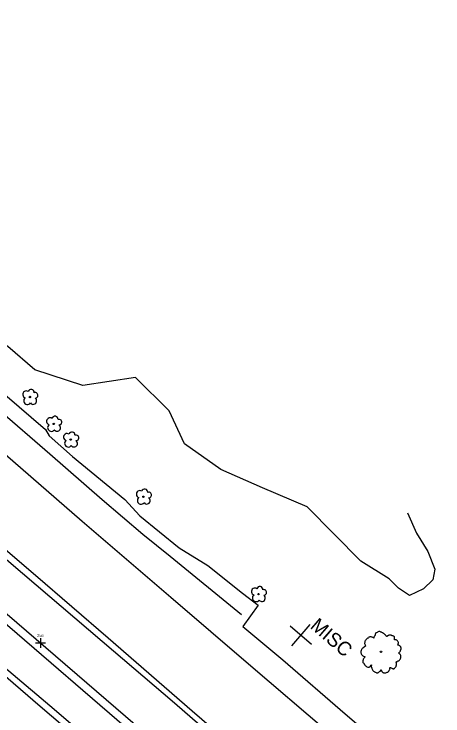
# Model space of a CAD drawing. Extents: x 2076109 to 2080761, y 592812 to 596750.
# Drawn here: x 2079834.4 to 2079987.8, y 593575.6 to 593826.9 of the extents above; entities that cross this region are included whole.
import ezdxf

# ---------------------------------------------------------------- set-up
doc = ezdxf.new("R2010")
doc.units = 0
for name, color, linetype in [('Default', 7, 'Continuous'), ('RD_EX_GuardRail', 7, 'Continuous'), ('RD_EX_Misc', 7, 'Continuous'), ('RD_EX_Misc_txCode', 7, 'Continuous'), ('RD_EX_Road', 7, 'Continuous'), ('RD_EX_VEG', 7, 'Continuous'), ('RD_HC_Cl', 7, 'Continuous')]:
    doc.layers.add(name, color=color, linetype=linetype)

msp = doc.modelspace()

# ---------------------------------------------------------------- linework, layer by layer
at = {"layer": 'Default'}
for p, q in [((2079843.82, 593603.43), (2079843.82, 593599.93)), ((2079843.82, 593603.43), (2079843.82, 593599.93)), ((2079845.57, 593601.68), (2079842.07, 593601.68)), ((2079845.57, 593601.68), (2079842.07, 593601.68))]:
    msp.add_line(p, q, dxfattribs=at)
at = {"layer": 'RD_EX_GuardRail'}
for points in [[(2080184.35, 593305.04), (2080148.2, 593335.86), (2080111.67, 593367.26), (2080075.44, 593398.3), (2080039.84, 593429.28), (2080003.46, 593460.74), (2079967.36, 593491.67), (2079919.17, 593532.83), (2079871.19, 593574.23), (2079835.53, 593605.02), (2079799.41, 593635.93), (2079763.16, 593666.95), (2079727.5, 593697.27), (2079690.37, 593729.2), (2079655.55, 593758.99), (2079608.01, 593799.67)], [(2079915.69, 593611.77), (2079890.2, 593632.66), (2079880.48, 593640.55), (2079865.92, 593652.95), (2079847.21, 593669.28), (2079828.34, 593685.59), (2079804.41, 593705.91), (2079785.94, 593721.98), (2079757.68, 593746.46), (2079723.46, 593776.29)], [(2079915.69, 593611.77), (2079890.2, 593632.66), (2079880.48, 593640.55), (2079865.92, 593652.95), (2079847.21, 593669.28), (2079828.34, 593685.59), (2079804.41, 593705.91), (2079785.94, 593721.98), (2079757.68, 593746.46), (2079723.46, 593776.29)]]:
    msp.add_lwpolyline(points, dxfattribs=at)
at = {"layer": 'RD_EX_Misc'}
for p, q in [((2079933.2, 593607.81), (2079940.76, 593601.27)), ((2079933.2, 593607.81), (2079940.76, 593601.27)), ((2079933.71, 593600.76), (2079940.25, 593608.33)), ((2079933.71, 593600.76), (2079940.25, 593608.33))]:
    msp.add_line(p, q, dxfattribs=at)
for points in [[(2080217.04, 593337.18), (2080172.52, 593375.33), (2080138.87, 593404.33), (2080108.48, 593430.29), (2080078.14, 593456.52), (2080038.92, 593490.11), (2080009.05, 593515.98), (2079977.29, 593543.26), (2079946.15, 593570.28), (2079919.11, 593593.43), (2079890.41, 593617.97), (2079858.75, 593645.26), (2079821.86, 593677.15), (2079782.12, 593711.42), (2079735.64, 593751.71), (2079701.45, 593781.37), (2079664.35, 593813.72), (2079643.76, 593831.64)], [(2079627.11, 593812.28), (2079655.96, 593786.97), (2079692.98, 593754.86), (2079726.56, 593725.77), (2079758.83, 593697.63), (2079788.04, 593672.28), (2079811.24, 593652.3), (2079842, 593625.98), (2079868.07, 593603.53), (2079898.03, 593577.49), (2079923.97, 593555.11), (2079945.84, 593536.38), (2079972.92, 593513.01), (2079994.98, 593494.07), (2080016.85, 593475.02), (2080049.11, 593447.31), (2080079.81, 593420.95), (2080112.25, 593393.22), (2080144.25, 593365.64), (2080177.02, 593337.45), (2080203.16, 593314.91)], [(2080178.72, 593290.98), (2080145.52, 593319.67), (2080116.25, 593344.84), (2080082.12, 593374.03), (2080051.53, 593400.34), (2080021.2, 593426.66), (2079989.82, 593453.61), (2079954.27, 593484.21), (2079917.77, 593515.59), (2079872.88, 593554.03), (2079843.75, 593579.04), (2079811.01, 593607.11), (2079771.89, 593640.76), (2079736.28, 593671.46), (2079708.41, 593695.19), (2079678.65, 593720.6), (2079637.6, 593755.82), (2079606.82, 593782.2)]]:
    msp.add_lwpolyline(points, dxfattribs=at)
at = {"layer": 'RD_EX_Road'}
for points in [[(2079915.58, 593559.4), (2079891.77, 593580.17), (2079865.9, 593602.21), (2079832.47, 593630.76), (2079804.37, 593655.14), (2079781.34, 593675), (2079764.28, 593689.81), (2079743.82, 593707.18), (2079725.61, 593722.92), (2079710.62, 593736.11), (2079695.41, 593749.27), (2079683.78, 593759.65), (2079664.93, 593775.72), (2079643.32, 593794.49), (2079625.35, 593810.82)], [(2079603.88, 593788.4), (2079630.41, 593765.74), (2079649.64, 593748.83), (2079670, 593731.78), (2079695.31, 593710.54), (2079705.57, 593701.2), (2079723.39, 593685.71), (2079744.81, 593667.42), (2079757.22, 593656.6), (2079776.93, 593639.55), (2079797.54, 593621.87), (2079819.28, 593602.83), (2079847.19, 593579.3), (2079876.99, 593553.77)], [(2079831.04, 593690.71), (2079845.61, 593678.16), (2079846.92, 593675.92), (2079855.23, 593668.45), (2079873.95, 593653.14), (2079879.4, 593647.23), (2079893.41, 593635.8), (2079903.73, 593629.47), (2079916.08, 593619.54), (2079921.67, 593615.3), (2079916.27, 593607.61), (2079930.48, 593595.65), (2079952.79, 593576.41), (2079973.53, 593558.52)]]:
    msp.add_lwpolyline(points, dxfattribs=at)
at = {"layer": 'RD_EX_VEG'}
for points in [[(2079968.58, 593624.66), (2079958.38, 593631.05), (2079939.2, 593650.42), (2079923.3, 593657.31), (2079908.32, 593663.78), (2079895.34, 593672.97), (2079889.9, 593684.89), (2079877.81, 593696.83), (2079858.95, 593693.87), (2079841.76, 593699.48), (2079832.11, 593707.82), (2079816.9, 593723.01), (2079799.06, 593733.44), (2079782.58, 593737.31), (2079774.16, 593743.85), (2079774.4, 593750.13), (2079779.63, 593760.24), (2079784.95, 593777.32), (2079790.58, 593800.97), (2079790.86, 593805.75)], [(2079968.58, 593624.66), (2079958.38, 593631.05), (2079939.2, 593650.42), (2079923.3, 593657.31), (2079908.32, 593663.78), (2079895.34, 593672.97), (2079889.9, 593684.89), (2079877.81, 593696.83), (2079858.95, 593693.87), (2079841.76, 593699.48), (2079832.11, 593707.82), (2079816.9, 593723.01), (2079799.06, 593733.44), (2079782.58, 593737.31), (2079774.16, 593743.85), (2079774.4, 593750.13), (2079779.63, 593760.24), (2079784.95, 593777.32), (2079790.58, 593800.97), (2079790.86, 593805.75)], [(2079975.08, 593648.34), (2079978.3, 593640.99), (2079982.45, 593634.44), (2079984.88, 593628.11), (2079984.16, 593624.28), (2079980.91, 593621.16), (2079975.82, 593618.71), (2079971.96, 593621.31), (2079968.58, 593624.66)], [(2079975.08, 593648.34), (2079978.3, 593640.99), (2079982.45, 593634.44), (2079984.88, 593628.11), (2079984.16, 593624.28), (2079980.91, 593621.16), (2079975.82, 593618.71), (2079971.96, 593621.31), (2079968.58, 593624.66)]]:
    msp.add_lwpolyline(points, dxfattribs=at)
for centre, radius in [((2079840.01, 593689.79), 0.25), ((2079840.01, 593689.79), 0.25), ((2079848.55, 593680.18), 0.25), ((2079848.55, 593680.18), 0.25), ((2079854.62, 593674.56), 0.25), ((2079854.62, 593674.56), 0.25), ((2079880.65, 593654.09), 0.25), ((2079880.65, 593654.09), 0.25), ((2079921.82, 593619.23), 0.25), ((2079921.82, 593619.23), 0.25), ((2079965.64, 593598.57), 0.25), ((2079965.64, 593598.57), 0.25), ((2079965.62, 593598.56), 0.0001), ((2079965.62, 593598.56), 0.0001)]:
    msp.add_circle(centre, radius, dxfattribs=at)
for centre, radius, start, end in [((2079840.47, 593691.43), 1.08, 354.1438, 163.9235), ((2079840.47, 593691.43), 1.08, 354.1438, 163.9235), ((2079838.72, 593690.69), 1.26, 55.6193, 253.9015), ((2079838.72, 593690.69), 1.26, 55.6193, 253.9015), ((2079841.91, 593690.39), 0.995, 267.9301, 111.2143), ((2079841.91, 593690.39), 0.995, 267.9301, 111.2143), ((2079839.15, 593688.42), 1.32, 126.0502, 324.9265), ((2079839.15, 593688.42), 1.32, 126.0502, 324.9265), ((2079841.22, 593688.37), 1.22, 215.7342, 57.2722), ((2079841.22, 593688.37), 1.22, 215.7342, 57.2722), ((2079847.27, 593681.08), 1.26, 55.6193, 253.9015), ((2079847.27, 593681.08), 1.26, 55.6193, 253.9015), ((2079849.02, 593681.82), 1.08, 354.1438, 163.9235), ((2079849.02, 593681.82), 1.08, 354.1438, 163.9235), ((2079847.7, 593678.81), 1.32, 126.0502, 324.9265), ((2079847.7, 593678.81), 1.32, 126.0502, 324.9265), ((2079849.76, 593678.76), 1.22, 215.7342, 57.2722), ((2079849.76, 593678.76), 1.22, 215.7342, 57.2722), ((2079850.46, 593680.78), 0.995, 267.9301, 111.2143), ((2079850.46, 593680.78), 0.995, 267.9301, 111.2143), ((2079855.09, 593676.2), 1.08, 354.1438, 163.9235), ((2079855.09, 593676.2), 1.08, 354.1438, 163.9235), ((2079853.34, 593675.46), 1.26, 55.6193, 253.9015), ((2079853.34, 593675.46), 1.26, 55.6193, 253.9015), ((2079856.53, 593675.16), 0.995, 267.9301, 111.2143), ((2079856.53, 593675.16), 0.995, 267.9301, 111.2143), ((2079853.77, 593673.19), 1.32, 126.0502, 324.9265), ((2079853.77, 593673.19), 1.32, 126.0502, 324.9265), ((2079855.83, 593673.14), 1.22, 215.7342, 57.2722), ((2079855.83, 593673.14), 1.22, 215.7342, 57.2722), ((2079879.36, 593655), 1.26, 55.6193, 253.9015), ((2079879.36, 593655), 1.26, 55.6193, 253.9015), ((2079881.11, 593655.73), 1.08, 354.1438, 163.9235), ((2079881.11, 593655.73), 1.08, 354.1438, 163.9235), ((2079882.55, 593654.7), 0.995, 267.9301, 111.2143), ((2079882.55, 593654.7), 0.995, 267.9301, 111.2143), ((2079879.79, 593652.72), 1.32, 126.0502, 324.9265), ((2079879.79, 593652.72), 1.32, 126.0502, 324.9265), ((2079881.86, 593652.68), 1.22, 215.7342, 57.2722), ((2079881.86, 593652.68), 1.22, 215.7342, 57.2722), ((2079922.29, 593620.87), 1.08, 354.1438, 163.9235), ((2079922.29, 593620.87), 1.08, 354.1438, 163.9235), ((2079920.54, 593620.13), 1.26, 55.6193, 253.9015), ((2079920.54, 593620.13), 1.26, 55.6193, 253.9015), ((2079923.72, 593619.83), 0.995, 267.9301, 111.2143), ((2079923.72, 593619.83), 0.995, 267.9301, 111.2143), ((2079920.96, 593617.86), 1.32, 126.0502, 324.9265), ((2079920.96, 593617.86), 1.32, 126.0502, 324.9265), ((2079923.03, 593617.81), 1.22, 215.7342, 57.2722), ((2079923.03, 593617.81), 1.22, 215.7342, 57.2722)]:
    msp.add_arc(centre, radius, start, end, dxfattribs=at)
for points in [[(2079970.43, 593603.9), (2079970.22, 593604.12), (2079969.91, 593604.25), (2079969.65, 593604.34), (2079969.43, 593604.43), (2079969.2, 593604.5), (2079968.85, 593604.57), (2079968.55, 593604.56), (2079968.3, 593604.46), (2079968.11, 593604.32), (2079967.89, 593604.14), (2079967.78, 593604.01), (2079967.67, 593604.07), (2079967.57, 593604.19), (2079967.43, 593604.41), (2079967.24, 593604.57), (2079967.05, 593604.74), (2079966.77, 593604.95), (2079966.51, 593605.18), (2079966.27, 593605.32), (2079965.99, 593605.49), (2079965.62, 593605.64), (2079965.28, 593605.78), (2079964.89, 593605.78), (2079964.39, 593605.59), (2079964.06, 593605.4), (2079963.79, 593605.31), (2079963.61, 593604.88), (2079963.51, 593604.5), (2079963.4, 593604.33), (2079963.18, 593603.96), (2079963.11, 593603.72), (2079963.07, 593603.49), (2079963, 593603.52), (2079962.68, 593603.73), (2079962.39, 593603.85), (2079961.92, 593603.96), (2079961.6, 593603.93), (2079961.31, 593603.75), (2079961.07, 593603.5), (2079960.86, 593603.42), (2079960.62, 593603.26), (2079960.56, 593603.22), (2079960.31, 593603), (2079960.09, 593602.6), (2079959.88, 593602.32), (2079959.82, 593602.07), (2079959.82, 593601.84), (2079959.79, 593601.53), (2079959.95, 593601.1), (2079960.13, 593600.81), (2079960.26, 593600.66), (2079959.8, 593600.4), (2079959.54, 593600.17), (2079959.18, 593599.95), (2079959.13, 593599.89), (2079958.78, 593599.56), (2079958.69, 593599.22), (2079958.5, 593598.89), (2079958.48, 593598.6), (2079958.49, 593598.2), (2079958.59, 593597.81), (2079958.89, 593597.39), (2079959.21, 593597.15), (2079959.76, 593596.91), (2079960, 593596.8), (2079959.86, 593596.68), (2079959.64, 593596.38), (2079959.36, 593596.06), (2079959.26, 593595.72), (2079959.16, 593595.44), (2079959.11, 593595.16), (2079959.2, 593594.77), (2079959.46, 593594.46), (2079959.68, 593594.07), (2079959.97, 593593.71), (2079960.33, 593593.37), (2079960.89, 593593.09), (2079961.18, 593593.01), (2079961.37, 593593.07), (2079961.76, 593593.22), (2079961.87, 593593.43), (2079962.28, 593593.87), (2079962.24, 593593.67), (2079962.15, 593593.29), (2079962.33, 593592.73), (2079962.52, 593592.34), (2079962.78, 593591.92), (2079962.96, 593591.66), (2079963.36, 593591.41), (2079963.7, 593591.22), (2079964.06, 593591.07), (2079964.47, 593591.08), (2079964.78, 593591.18), (2079965, 593591.35), (2079965.3, 593591.59), (2079965.45, 593591.69)], [(2079970.43, 593603.9), (2079970.22, 593604.12), (2079969.91, 593604.25), (2079969.65, 593604.34), (2079969.43, 593604.43), (2079969.2, 593604.5), (2079968.85, 593604.57), (2079968.55, 593604.56), (2079968.3, 593604.46), (2079968.11, 593604.32), (2079967.89, 593604.14), (2079967.78, 593604.01), (2079967.67, 593604.07), (2079967.57, 593604.19), (2079967.43, 593604.41), (2079967.24, 593604.57), (2079967.05, 593604.74), (2079966.77, 593604.95), (2079966.51, 593605.18), (2079966.27, 593605.32), (2079965.99, 593605.49), (2079965.62, 593605.64), (2079965.28, 593605.78), (2079964.89, 593605.78), (2079964.39, 593605.59), (2079964.06, 593605.4), (2079963.79, 593605.31), (2079963.61, 593604.88), (2079963.51, 593604.5), (2079963.4, 593604.33), (2079963.18, 593603.96), (2079963.11, 593603.72), (2079963.07, 593603.49), (2079963, 593603.52), (2079962.68, 593603.73), (2079962.39, 593603.85), (2079961.92, 593603.96), (2079961.6, 593603.93), (2079961.31, 593603.75), (2079961.07, 593603.5), (2079960.86, 593603.42), (2079960.62, 593603.26), (2079960.56, 593603.22), (2079960.31, 593603), (2079960.09, 593602.6), (2079959.88, 593602.32), (2079959.82, 593602.07), (2079959.82, 593601.84), (2079959.79, 593601.53), (2079959.95, 593601.1), (2079960.13, 593600.81), (2079960.26, 593600.66), (2079959.8, 593600.4), (2079959.54, 593600.17), (2079959.18, 593599.95), (2079959.13, 593599.89), (2079958.78, 593599.56), (2079958.69, 593599.22), (2079958.5, 593598.89), (2079958.48, 593598.6), (2079958.49, 593598.2), (2079958.59, 593597.81), (2079958.89, 593597.39), (2079959.21, 593597.15), (2079959.76, 593596.91), (2079960, 593596.8), (2079959.86, 593596.68), (2079959.64, 593596.38), (2079959.36, 593596.06), (2079959.26, 593595.72), (2079959.16, 593595.44), (2079959.11, 593595.16), (2079959.2, 593594.77), (2079959.46, 593594.46), (2079959.68, 593594.07), (2079959.97, 593593.71), (2079960.33, 593593.37), (2079960.89, 593593.09), (2079961.18, 593593.01), (2079961.37, 593593.07), (2079961.76, 593593.22), (2079961.87, 593593.43), (2079962.28, 593593.87), (2079962.24, 593593.67), (2079962.15, 593593.29), (2079962.33, 593592.73), (2079962.52, 593592.34), (2079962.78, 593591.92), (2079962.96, 593591.66), (2079963.36, 593591.41), (2079963.7, 593591.22), (2079964.06, 593591.07), (2079964.47, 593591.08), (2079964.78, 593591.18), (2079965, 593591.35), (2079965.3, 593591.59), (2079965.45, 593591.69)], [(2079965.45, 593591.69), (2079965.51, 593591.87), (2079965.64, 593592.09), (2079965.68, 593592.02), (2079965.78, 593591.87), (2079965.9, 593591.6), (2079966.02, 593591.39), (2079966.29, 593591.2), (2079966.56, 593591.09), (2079967.08, 593591.01), (2079967.6, 593591.19), (2079968.07, 593591.31), (2079968.34, 593591.51), (2079968.45, 593591.71), (2079968.75, 593592.1), (2079968.77, 593592.42), (2079968.81, 593592.55), (2079968.99, 593592.92), (2079969.08, 593592.91), (2079969.32, 593592.77), (2079969.69, 593592.62), (2079969.98, 593592.53), (2079970.26, 593592.52), (2079970.47, 593592.64), (2079970.71, 593592.96), (2079971.01, 593593.23), (2079971.05, 593593.39), (2079971.07, 593593.57), (2079971.15, 593593.77), (2079971.13, 593593.98), (2079971.15, 593594.16), (2079971.14, 593594.3), (2079971.15, 593594.49), (2079971.1, 593594.7), (2079971.02, 593594.84), (2079971.08, 593594.98), (2079971.32, 593595.04), (2079971.42, 593595.08), (2079971.59, 593595.23), (2079971.99, 593595.35), (2079972.29, 593595.62), (2079972.53, 593595.98), (2079972.67, 593596.22), (2079972.74, 593596.52), (2079972.75, 593596.84), (2079972.77, 593597.06), (2079972.72, 593597.27), (2079972.55, 593597.57), (2079972.4, 593597.77), (2079972.13, 593598), (2079972.01, 593598.17), (2079972.07, 593598.19), (2079972.16, 593598.31), (2079972.34, 593598.51), (2079972.58, 593598.9), (2079972.79, 593599.38), (2079972.81, 593599.4), (2079972.9, 593599.65), (2079972.86, 593599.95), (2079972.79, 593600.14), (2079972.72, 593600.37), (2079972.55, 593600.55), (2079972.32, 593600.74), (2079972.08, 593600.89), (2079971.87, 593600.94), (2079971.65, 593600.96), (2079971.69, 593601.12), (2079971.81, 593601.42), (2079971.87, 593601.56), (2079971.87, 593601.79), (2079971.83, 593602.09), (2079971.58, 593602.48), (2079971.05, 593602.83), (2079970.7, 593602.88), (2079970.47, 593602.84), (2079970.51, 593602.97), (2079970.49, 593603.25), (2079970.53, 593603.45), (2079970.48, 593603.66), (2079970.43, 593603.83), (2079970.39, 593603.93)], [(2079965.45, 593591.69), (2079965.51, 593591.87), (2079965.64, 593592.09), (2079965.68, 593592.02), (2079965.78, 593591.87), (2079965.9, 593591.6), (2079966.02, 593591.39), (2079966.29, 593591.2), (2079966.56, 593591.09), (2079967.08, 593591.01), (2079967.6, 593591.19), (2079968.07, 593591.31), (2079968.34, 593591.51), (2079968.45, 593591.71), (2079968.75, 593592.1), (2079968.77, 593592.42), (2079968.81, 593592.55), (2079968.99, 593592.92), (2079969.08, 593592.91), (2079969.32, 593592.77), (2079969.69, 593592.62), (2079969.98, 593592.53), (2079970.26, 593592.52), (2079970.47, 593592.64), (2079970.71, 593592.96), (2079971.01, 593593.23), (2079971.05, 593593.39), (2079971.07, 593593.57), (2079971.15, 593593.77), (2079971.13, 593593.98), (2079971.15, 593594.16), (2079971.14, 593594.3), (2079971.15, 593594.49), (2079971.1, 593594.7), (2079971.02, 593594.84), (2079971.08, 593594.98), (2079971.32, 593595.04), (2079971.42, 593595.08), (2079971.59, 593595.23), (2079971.99, 593595.35), (2079972.29, 593595.62), (2079972.53, 593595.98), (2079972.67, 593596.22), (2079972.74, 593596.52), (2079972.75, 593596.84), (2079972.77, 593597.06), (2079972.72, 593597.27), (2079972.55, 593597.57), (2079972.4, 593597.77), (2079972.13, 593598), (2079972.01, 593598.17), (2079972.07, 593598.19), (2079972.16, 593598.31), (2079972.34, 593598.51), (2079972.58, 593598.9), (2079972.79, 593599.38), (2079972.81, 593599.4), (2079972.9, 593599.65), (2079972.86, 593599.95), (2079972.79, 593600.14), (2079972.72, 593600.37), (2079972.55, 593600.55), (2079972.32, 593600.74), (2079972.08, 593600.89), (2079971.87, 593600.94), (2079971.65, 593600.96), (2079971.69, 593601.12), (2079971.81, 593601.42), (2079971.87, 593601.56), (2079971.87, 593601.79), (2079971.83, 593602.09), (2079971.58, 593602.48), (2079971.05, 593602.83), (2079970.7, 593602.88), (2079970.47, 593602.84), (2079970.51, 593602.97), (2079970.49, 593603.25), (2079970.53, 593603.45), (2079970.48, 593603.66), (2079970.43, 593603.83), (2079970.39, 593603.93)]]:
    msp.add_spline(points, degree=3, dxfattribs=at)
at = {"layer": 'RD_HC_Cl'}
msp.add_line((2079511.94, 593887.33), (2080761.16, 592812.48), dxfattribs=at)

# ---------------------------------------------------------------- texts
at = {"layer": 'Default'}
msp.add_text('256', height=1, dxfattribs=at).set_placement((2079842.62, 593603.88))
msp.add_text('256', height=1, dxfattribs=at).set_placement((2079842.62, 593603.88))
at = {"layer": 'RD_EX_Misc_txCode'}
msp.add_text(' MISC', height=5, rotation=319.1675, dxfattribs=at).set_placement((2079938.61, 593608.52))
msp.add_text(' MISC', height=5, rotation=319.1675, dxfattribs=at).set_placement((2079938.61, 593608.52))

doc.saveas('drawing.dxf')
